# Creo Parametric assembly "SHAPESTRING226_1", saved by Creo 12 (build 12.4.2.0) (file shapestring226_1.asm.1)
Units: Custom; MM, KILOGRAM, SECS

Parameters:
  PTC_WM_ITERATION = "0"
  PTC_WM_VERSION = "-.0"
  PTC_WM_LIFECYCLE_STATE = "In Work"
  PTC_WM_LIFECYCLE = "MO_CADDocument"
  PTC_WM_CREATED_BY = "Maximilian Roepper (Z0017RMS: MO)"
  PTC_WM_CREATED_ON = "18-Sep-26 11:36:42 AM"
  PTC_WM_MODIFIED_BY = "Maximilian Roepper (Z0017RMS: MO)"
  PTC_WM_MODIFIED_ON = "18-Sep-26 11:36:46 AM"
  PDMLINKNUMBER = "PDM000071455056"
  PTC_WM_NAME = "shapestring226_1.asm"
  PTC_WM_NUMBER = "PDM000071455056"

Other parameters: WEIGHT, WEIGHT_FACTOR, WEIGHT_ADD, MC_ERRORS, SUPPLIER, ISPOSITIONINGASSEMBLY

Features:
  1. coordinate system
  2. imported feature
  3. component "SHAPESTRING088_1"
  4. component "SHAPESTRING225_1"

Other named items: DRW_VIEW_ORG, ROUGH-GROB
